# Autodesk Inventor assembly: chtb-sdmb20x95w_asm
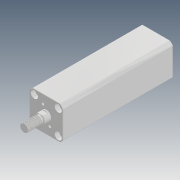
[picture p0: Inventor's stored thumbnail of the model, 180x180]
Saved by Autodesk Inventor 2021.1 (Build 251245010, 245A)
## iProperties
Company: Microsoft
Created: 2018-05
Part Number: chtb-sdmb20x95w_asm
Description: STEP AP214
Document SubType Name: Assembly
Designer: user
Title: chtb-sdmb20x95w_asm.STEP
Author: Windows
Revision Number: ÈÎºÎ
Sending System: SolidWorks 2015
Preprocessor: SwSTEP 2.0
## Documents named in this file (4)
- D:\Vault_2016\Projekty\Clamptek\Hydraulic\CHTB\CHTB-20\Inventor\CHTB-SDMB20x95W\chtb-sdmb20x95w_asm.iam
- D:\Vault_2016\Projekty\Clamptek\Hydraulic\CHTB\CHTB-20\Inventor\CHTB-SDMB20x95W\CHTB-SDMB20X95NBT.ipt
- D:\Vault_2016\Projekty\Clamptek\Hydraulic\CHTB\CHTB-20\Inventor\CHTB-SDMB20x95W\CHTB-SDMB20X95WHSG.ipt
- D:\Vault_2016\Projekty\Clamptek\Hydraulic\CHTB\CHTB-20\Inventor\CHTB-SDMB20x95W\QG_3.ipt
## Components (3 placed, 3 different names)
1. CHTB-SDMB20X95NBT_1
2. CHTB-SDMB20X95WHSG_2
3. QG_3_3
